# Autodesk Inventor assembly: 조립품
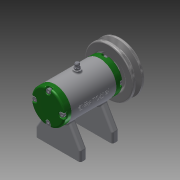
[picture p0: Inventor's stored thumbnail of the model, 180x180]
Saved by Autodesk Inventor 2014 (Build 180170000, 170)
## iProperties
Created: 2018-05
Part Number: 조립품
Document SubType Name: Assembly
Designer: net
Author: net
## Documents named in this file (16)
- C:\Users\net\Desktop\480507V1021\답안조립품.iam
- C:\Users\net\Desktop\480507V1021\본체.ipt
- C:\Users\net\Desktop\480507V1021\축.ipt
- C:\Users\net\Desktop\480507V1021\베어링 6002.ipt
- C:\Users\net\Desktop\480507V1021\뒤커버.ipt
- C:\Users\net\Desktop\480507V1021\앞커버.ipt
- C:\Users\net\Desktop\480507V1021\오일 실 15 25 7.ipt
- C:\Users\net\Desktop\480507V1021\키 3x3x12.ipt
- C:\Users\net\Desktop\480507V1021\V벨트풀리.ipt
- C:\Users\net\Desktop\480507V1021\와셔 8x17.ipt
- C:\Users\net\Desktop\480507V1021\스프링와셔 8.ipt
- C:\Users\net\Desktop\480507V1021\너트 M8.ipt
- C:\Users\net\Desktop\480507V1021\니플 M6x0.75.ipt
- C:\Users\net\Desktop\480507V1021\와셔 6x11.5.ipt
- C:\Users\net\Desktop\480507V1021\볼트 M6x8.ipt
- C:\Users\net\Desktop\480507V1021\볼트 M4x12.ipt
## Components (1 placed, 1 different names)
1. V벨트풀리:1
